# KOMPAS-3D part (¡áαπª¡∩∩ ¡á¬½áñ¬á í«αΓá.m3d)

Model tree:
1. Эскиз:1
2. Операция выдавливания:1
     Расстояние 1 = 0.5
3. Эскиз:2
4. Вырезать элемент выдавливания:1
     Расстояние 1 = 10

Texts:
  наружняя накладка борта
